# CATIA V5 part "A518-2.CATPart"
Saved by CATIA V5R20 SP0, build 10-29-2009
Part number: A518-2
Source: Unknown
Property "ARTICLENO": "A518-2"
Property "BOMINFO": "A518-2"
Property "CODE": "A518-2"
Property "D": "40.000"
Property "H": "32.000"
Property "H1": "50.000"
Property "L": "60.000"
Property "L1": "45.000"
Property "LINA": "A518-2"
Property "NB": "A518-2"
Property "NBSYN": "$CODE."
Property "NN": "A518"
Property "NT": "Shock Absorber for Pad Retainer Pins"
Property "PINDIA": "40.000"
Property "R": "18.000"
Property "SUPPLIER": "CF"
Bounding box of the stored display mesh (mm): x -20 to 16.267, y 0 to 60, z -19.989 to 19.989
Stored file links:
  C:\Users\Utente\Desktop\3D files A518\A518-2.CATPart
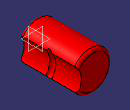
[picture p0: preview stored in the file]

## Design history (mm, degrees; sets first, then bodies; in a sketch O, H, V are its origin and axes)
Body1 "Geometry.1" (main body)
  Solid1 "A518-2.catpart": solid without history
